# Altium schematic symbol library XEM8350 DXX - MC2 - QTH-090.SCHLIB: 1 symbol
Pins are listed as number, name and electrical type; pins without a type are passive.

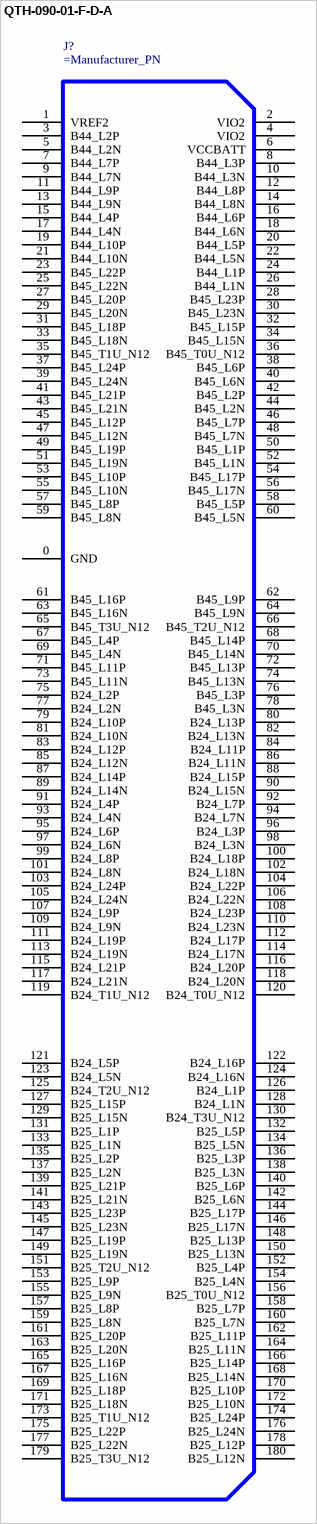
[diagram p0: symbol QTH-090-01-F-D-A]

## QTH-090-01-F-D-A
designator J?
0.5mm Double Row High Speed Socket Assembly
pins: 0 GND (power), 1 VREF2, 2 VIO2, 3 B44_L2P, 4 VIO2, 5 B44_L2N, 6 VCCBATT, 7 B44_L7P, 8 B44_L3P, 9 B44_L7N, 10 B44_L3N, 11 B44_L9P, 12 B44_L8P, 13 B44_L9N, 14 B44_L8N, 15 B44_L4P, 16 B44_L6P, 17 B44_L4N, 18 B44_L6N, 19 B44_L10P, 20 B44_L5P, 21 B44_L10N, 22 B44_L5N, 23 B45_L22P, 24 B44_L1P, 25 B45_L22N, 26 B44_L1N, 27 B45_L20P, 28 B45_L23P, 29 B45_L20N, 30 B45_L23N, 31 B45_L18P, 32 B45_L15P, 33 B45_L18N, 34 B45_L15N, 35 B45_T1U_N12, 36 B45_T0U_N12, 37 B45_L24P, 38 B45_L6P, 39 B45_L24N, 40 B45_L6N, 41 B45_L21P, 42 B45_L2P, 43 B45_L21N, 44 B45_L2N, 45 B45_L12P, 46 B45_L7P, 47 B45_L12N, 48 B45_L7N, 49 B45_L19P, 50 B45_L1P, 51 B45_L19N, 52 B45_L1N, 53 B45_L10P, 54 B45_L17P, 55 B45_L10N, 56 B45_L17N, 57 B45_L8P, 58 B45_L5P, 59 B45_L8N, 60 B45_L5N, 61 B45_L16P, 62 B45_L9P, 63 B45_L16N, 64 B45_L9N, 65 B45_T3U_N12, 66 B45_T2U_N12, 67 B45_L4P, 68 B45_L14P, 69 B45_L4N, 70 B45_L14N, 71 B45_L11P, 72 B45_L13P, 73 B45_L11N, 74 B45_L13N, 75 B24_L2P, 76 B45_L3P, 77 B24_L2N, 78 B45_L3N, 79 B24_L10P, 80 B24_L13P, 81 B24_L10N, 82 B24_L13N, 83 B24_L12P, 84 B24_L11P, 85 B24_L12N, 86 B24_L11N, 87 B24_L14P, 88 B24_L15P, 89 B24_L14N, 90 B24_L15N, 91 B24_L4P, 92 B24_L7P, 93 B24_L4N, 94 B24_L7N, 95 B24_L6P, 96 B24_L3P, 97 B24_L6N, 98 B24_L3N, 99 B24_L8P, 100 B24_L18P, 101 B24_L8N, 102 B24_L18N, 103 B24_L24P, 104 B24_L22P, 105 B24_L24N, 106 B24_L22N, 107 B24_L9P, 108 B24_L23P, 109 B24_L9N, 110 B24_L23N, 111 B24_L19P, 112 B24_L17P, 113 B24_L19N, 114 B24_L17N, 115 B24_L21P, 116 B24_L20P, 117 B24_L21N, 118 B24_L20N, 119 B24_T1U_N12, 120 B24_T0U_N12, 121 B24_L5P, 122 B24_L16P, 123 B24_L5N, 124 B24_L16N, 125 B24_T2U_N12, 126 B24_L1P, 127 B25_L15P, 128 B24_L1N, 129 B25_L15N, 130 B24_T3U_N12, 131 B25_L1P, 132 B25_L5P, 133 B25_L1N, 134 B25_L5N, 135 B25_L2P, 136 B25_L3P, 137 B25_L2N, 138 B25_L3N, 139 B25_L21P, 140 B25_L6P, 141 B25_L21N, 142 B25_L6N, 143 B25_L23P, 144 B25_L17P, 145 B25_L23N, 146 B25_L17N, 147 B25_L19P, 148 B25_L13P, 149 B25_L19N, 150 B25_L13N, 151 B25_T2U_N12, 152 B25_L4P, 153 B25_L9P, 154 B25_L4N, 155 B25_L9N, 156 B25_T0U_N12, 157 B25_L8P, 158 B25_L7P, 159 B25_L8N, 160 B25_L7N, 161 B25_L20P, 162 B25_L11P, 163 B25_L20N, 164 B25_L11N, 165 B25_L16P, 166 B25_L14P, 167 B25_L16N, 168 B25_L14N, 169 B25_L18P, 170 B25_L10P, 171 B25_L18N, 172 B25_L10N, 173 B25_T1U_N12, 174 B25_L24P, 175 B25_L22P, 176 B25_L24N, 177 B25_L22N, 178 B25_L12P, 179 B25_T3U_N12, 180 B25_L12N
1 alternate drawing of the same symbol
